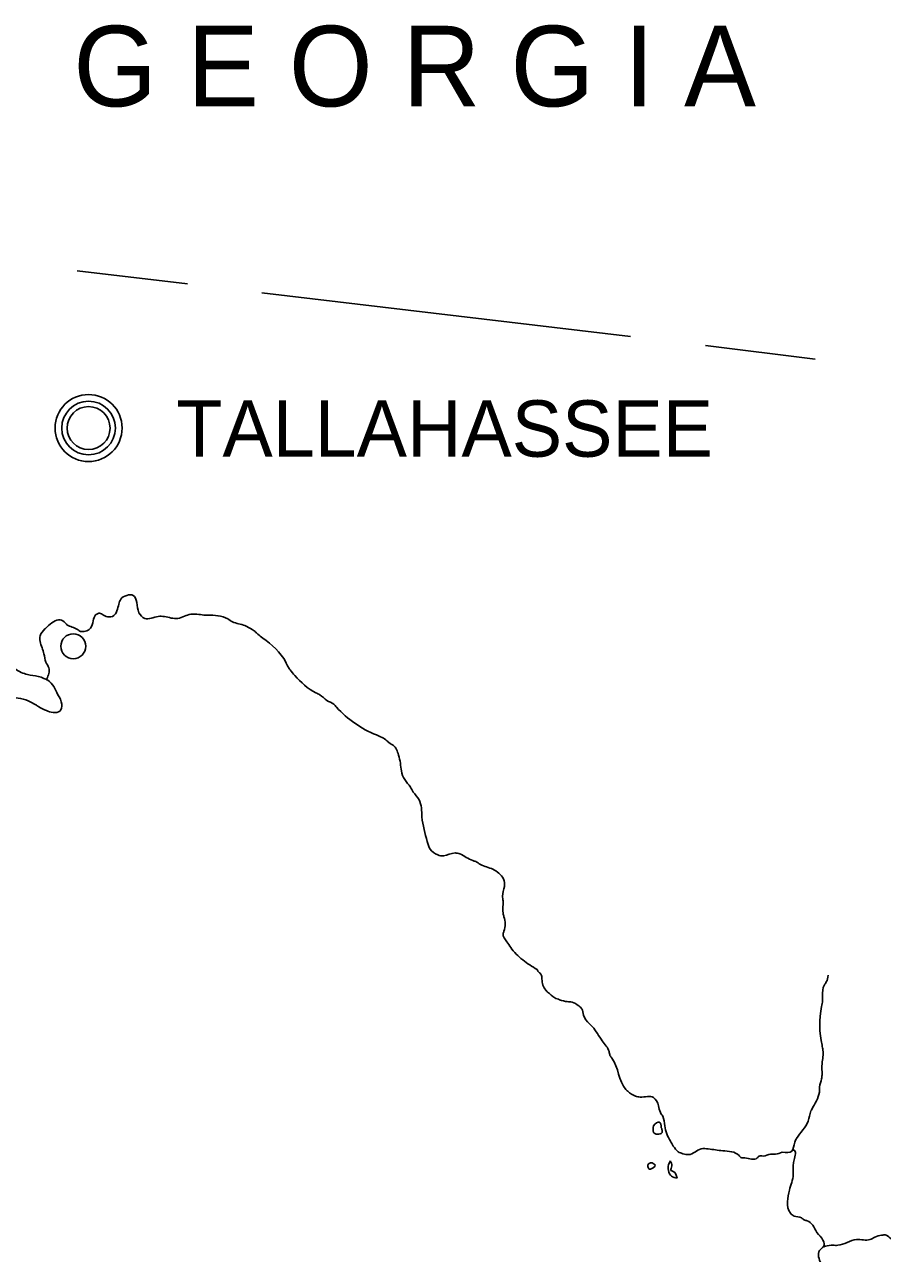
# Model space of a CAD drawing. Extents: x 384865 to 516869, y 1553900 to 1655899.
# Drawn here: x 485644 to 490473, y 1641531 to 1648449 of the extents above; entities that cross this region are included whole.
import ezdxf

# ---------------------------------------------------------------- set-up
doc = ezdxf.new("R2010")
doc.units = 0
doc.layers.add('V-ANNO-SYMB', color=7, linetype='Continuous')

msp = doc.modelspace()

# ---------------------------------------------------------------- linework, layer by layer
at = {"layer": 'V-ANNO-SYMB'}
for p, q in [((486561.4047428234, 1646989.260452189), (485939.67034240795, 1647062.938050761)), ((489053.9745422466, 1646692.9678515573), (486980.0559425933, 1646938.2142518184)), ((490093.7391423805, 1646564.1724524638), (489476.09794269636, 1646641.9432530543)), ((485831.44354296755, 1644676.0840512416), (485828.74354296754, 1644678.7840512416))]:
    msp.add_line(p, q, dxfattribs=at)
for centre, radius in [((486004.167942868, 1646177.2840512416), 188.66823551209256), ((486004.167942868, 1646177.2840512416), 150.9345884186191), ((486004.167942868, 1646177.2840512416), 120.74767074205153), ((485917.76794329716, 1644948.7840512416), 70.19999999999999)]:
    msp.add_circle(centre, radius, dxfattribs=at)
for points in [[(485769.3435429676, 1644765.1840512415), (485780.1435433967, 1644794.8840512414), (485780.14354296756, 1644827.2840512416), (485763.94354296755, 1644859.6840521), (485753.1435433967, 1644905.5840512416), (485731.5435429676, 1644975.7840512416), (485731.5435429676, 1645008.1840512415), (485758.5435429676, 1645045.9840512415), (485769.34354339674, 1645056.7840520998), (485807.1435425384, 1645086.4840512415), (485844.94354296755, 1645097.2840512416), (485871.94354296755, 1645081.0840520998), (485882.74354296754, 1645070.2840520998), (485942.14354296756, 1645043.2840529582), (485958.3435425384, 1645032.4840512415), (485979.9435425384, 1645032.4840512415), (486006.94354296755, 1645043.2840512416), (486028.5435429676, 1645081.0840520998), (486039.34354339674, 1645118.8840512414), (486050.1435425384, 1645129.6840512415), (486066.3435429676, 1645135.0840520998), (486087.94354296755, 1645124.2840512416), (486120.3435429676, 1645113.4840512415), (486152.74354296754, 1645126.9840512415), (486163.5435429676, 1645148.5840520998), (486174.3435425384, 1645186.3840512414), (486185.1435425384, 1645213.384052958), (486255.3435425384, 1645234.9840512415), (486287.7435433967, 1645137.7840520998), (486320.14354296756, 1645105.3840512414), (486395.74354296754, 1645116.1840512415), (486430.8435429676, 1645116.1840512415), (486506.4435433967, 1645105.3840521), (486544.24354296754, 1645118.8840512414), (486614.4435421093, 1645129.6840512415), (486652.24354253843, 1645124.2840512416), (486673.8435429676, 1645124.2840520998), (486787.24354253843, 1645102.6840521), (486814.24354253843, 1645086.4840512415), (486884.44354296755, 1645064.8840521), (486924.9435433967, 1645043.2840512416), (486946.5435425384, 1645027.0840520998), (486957.3435429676, 1645016.2840512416), (486984.3435429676, 1644994.6840512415), (487113.9435433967, 1644859.6840512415), (487127.4435425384, 1644832.6840512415), (487138.24354296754, 1644816.4840520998), (487165.24354296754, 1644784.0840512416), (487284.0435429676, 1644686.8840521), (487305.64354296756, 1644676.0840512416), (487346.14354296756, 1644643.6840512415), (487383.94354296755, 1644622.0840520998), (487400.1435433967, 1644605.8840512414), (487624.24354296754, 1644449.2840520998), (487683.6435425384, 1644416.8840512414), (487694.44354296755, 1644406.0840520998), (487721.4435425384, 1644389.8840512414), (487737.64354296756, 1644368.2840512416), (487748.44354296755, 1644335.8840521), (487759.24354296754, 1644289.9840512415), (487764.64354296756, 1644246.7840512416), (487783.5435429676, 1644198.1840521), (487815.94354296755, 1644154.9840512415), (487832.14354296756, 1644127.9840512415), (487864.5435433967, 1644084.7840520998), (487880.7435433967, 1643987.5840520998), (487910.44354296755, 1643849.884052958), (487926.6435433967, 1643806.6840512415), (487969.8435429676, 1643774.2840512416), (488002.24354296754, 1643768.8840512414), (488067.0435429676, 1643785.0840512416), (488094.0435429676, 1643779.6840521), (488166.94354296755, 1643741.8840512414), (488183.14354296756, 1643736.4840520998), (488210.14354296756, 1643720.2840512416), (488280.3435429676, 1643693.2840529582), (488312.74354253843, 1643671.6840512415), (488339.74354296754, 1643639.2840529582), (488345.14354296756, 1643596.0840520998), (488334.3435429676, 1643542.0840520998), (488337.0435433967, 1643515.0840512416), (488337.0435433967, 1643444.8840521), (488342.4435433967, 1643425.9840520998), (488342.44354296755, 1643344.9840520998), (488337.0435429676, 1643328.7840529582), (488358.64354296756, 1643285.5840520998), (488380.24354296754, 1643253.1840512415), (488447.74354296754, 1643182.9840512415), (488528.74354296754, 1643128.9840520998)], [(485831.44354296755, 1644676.0840512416), (485774.74354253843, 1644757.0840520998), (485753.1435425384, 1644767.8840521), (485720.74354253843, 1644778.6840512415), (485661.3435429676, 1644789.4840512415), (485591.14354296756, 1644821.8840512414), (485574.9435425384, 1644832.6840512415), (485547.9435433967, 1644838.0840512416), (485515.5435429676, 1644848.8840521), (485477.74354296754, 1644854.2840512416), (485418.3435425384, 1644854.2840512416), (485372.4435433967, 1644846.1840512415), (485350.8435429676, 1644873.1840512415), (485345.4435425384, 1644889.3840512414), (485269.8435425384, 1644932.5840520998), (485242.84354339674, 1644943.3840512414), (485167.24354296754, 1645002.7840512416), (485140.24354296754, 1645018.9840512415), (485115.94354296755, 1645040.5840512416), (485094.34354339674, 1645064.8840512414), (485061.94354296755, 1645108.0840512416)], [(484092.6435425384, 1644138.7840512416), (484108.8435429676, 1644165.7840512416), (484130.4435433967, 1644160.3840512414), (484168.24354296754, 1644165.7840512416), (484200.6435433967, 1644176.5840512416), (484216.84354339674, 1644200.8840512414), (484243.8435425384, 1644308.8840512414), (484270.8435425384, 1644325.0840512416), (484308.6435425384, 1644308.8840512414), (484341.0435425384, 1644308.8840521), (484373.4435433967, 1644349.3840512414), (484384.24354296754, 1644360.1840512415), (484389.6435433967, 1644322.3840512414), (484389.64354296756, 1644265.6840512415), (484376.14354296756, 1644217.0840512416), (484370.74354296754, 1644190.0840512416), (484370.74354296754, 1644163.0840512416), (484413.9435433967, 1644195.4840512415), (484440.9435425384, 1644238.6840512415), (484484.1435433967, 1644257.5840512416), (484619.14354296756, 1644257.5840520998), (484651.5435429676, 1644273.7840512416), (484716.3435425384, 1644338.5840512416), (484732.5435429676, 1644352.0840512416), (484759.5435429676, 1644368.2840512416), (484770.3435429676, 1644384.4840512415), (484829.74354296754, 1644422.2840512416), (484899.94354296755, 1644449.2840512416), (484943.1435425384, 1644468.1840512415), (485007.94354296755, 1644505.9840512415), (485229.3435429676, 1644584.2840512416), (485250.94354296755, 1644595.0840512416), (485564.14354296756, 1644657.1840512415), (485607.34354339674, 1644657.1840512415), (485664.0435429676, 1644640.9840512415), (485707.2435433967, 1644619.3840512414), (485723.4435433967, 1644608.5840512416), (485766.64354296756, 1644586.9840512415), (485804.4435425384, 1644576.1840512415), (485842.24354296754, 1644584.2840512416), (485853.0435433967, 1644622.0840512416), (485831.44354296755, 1644676.0840512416)], [(488528.74354296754, 1643128.9840520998), (488539.5435433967, 1643112.7840512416), (488550.3435429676, 1643101.9840512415), (488555.74354296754, 1643074.9840520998), (488577.34354382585, 1643012.8840512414), (488588.14354296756, 1643002.0840520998), (488628.6435433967, 1642969.6840521), (488655.64354296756, 1642958.884052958), (488698.84354339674, 1642948.0840520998), (488725.8435429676, 1642945.3840512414), (488763.6435433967, 1642923.7840512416), (488779.8435429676, 1642907.5840512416), (488790.6435438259, 1642872.4840520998), (488823.0435429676, 1642823.8840512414), (488839.2435433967, 1642807.6840512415), (488895.94354296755, 1642726.6840512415), (488933.74354296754, 1642667.2840520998), (488939.1435433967, 1642645.6840512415), (488949.94354296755, 1642629.4840529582), (489028.24354296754, 1642453.9840512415), (489039.0435429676, 1642443.1840521), (489082.2435433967, 1642416.1840521), (489109.2435433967, 1642410.7840520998), (489184.84354339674, 1642408.0840512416), (489211.8435429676, 1642362.1840521), (489222.6435433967, 1642324.384052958), (489236.1435438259, 1642302.7840512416), (489246.9435433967, 1642248.7840520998), (489279.3435429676, 1642162.384052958), (489295.5435433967, 1642135.384052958), (489322.5435433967, 1642102.9840520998), (489349.5435429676, 1642092.1840512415), (489381.94354296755, 1642086.7840529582), (489452.1435425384, 1642119.1840521), (489492.64354296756, 1642119.1840512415), (489573.6435433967, 1642108.3840512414), (489665.4435438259, 1642081.3840521), (489676.24354382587, 1642070.5840520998), (489697.8435429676, 1642067.8840512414), (489768.0435433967, 1642067.884052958), (489778.8435429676, 1642078.6840521), (489800.44354296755, 1642078.6840512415), (489843.64354296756, 1642089.4840520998), (489870.6435438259, 1642089.4840529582), (489908.4435438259, 1642100.2840512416)], [(489908.4435438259, 1642100.2840512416), (489962.4435433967, 1642105.6840512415), (489978.6435433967, 1642156.9840529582), (489989.4435433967, 1642178.5840520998), (490054.24354296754, 1642275.7840512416), (490070.4435433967, 1642332.4840512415), (490081.24354296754, 1642354.084052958), (490119.0435429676, 1642451.2840520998), (490119.0435433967, 1642467.4840520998), (490129.8435429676, 1642513.384052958), (490132.5435429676, 1642534.9840512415), (490132.5435425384, 1642599.7840529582), (490137.94354296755, 1642637.584052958), (490137.9435438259, 1642675.384052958), (490132.5435433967, 1642702.3840521), (490129.84354339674, 1642921.0840520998), (490135.24354296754, 1642953.4840512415), (490135.24354253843, 1642980.4840529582), (490146.0435433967, 1643042.584052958), (490156.84354339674, 1643058.7840520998), (490167.6435433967, 1643096.5840520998)], [(489184.84354339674, 1642210.9840520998), (489184.84354339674, 1642248.7840512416), (489217.24354296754, 1642270.3840521), (489228.04354382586, 1642237.9840512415)], [(489184.84354339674, 1642210.9840520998), (489198.3435429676, 1642202.8840512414), (489214.5435429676, 1642202.8840521), (489228.0435433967, 1642205.584052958), (489233.4435433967, 1642219.0840512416), (489228.04354382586, 1642237.9840512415)], [(489970.5435433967, 1642111.0840520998), (489973.2435433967, 1642111.084052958), (489975.9435433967, 1642057.0840520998), (489970.5435433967, 1642030.0840512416), (489970.54354382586, 1641976.084052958), (489948.94354296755, 1641886.9840529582), (489938.14354296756, 1641822.1840521), (489954.3435425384, 1641757.3840521), (489975.9435433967, 1641741.1840529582), (490016.4435433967, 1641730.3840521), (490032.6435433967, 1641719.5840520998), (490048.84354339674, 1641714.1840521), (490102.84354339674, 1641649.384052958)], [(489192.9435433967, 1642030.0840520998), (489187.5435433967, 1642016.5840520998), (489174.0435429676, 1642008.4840529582), (489160.5435433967, 1642005.7840529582), (489152.4435433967, 1642019.2840529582), (489155.1435433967, 1642035.4840529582)], [(489155.1435433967, 1642035.4840529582), (489171.3435429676, 1642040.8840521), (489192.9435433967, 1642030.0840520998)], [(489279.34354339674, 1642051.6840529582), (489268.54354382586, 1642030.0840520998), (489268.5435433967, 1641997.6840529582), (489284.7435433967, 1641965.2840512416), (489317.1435433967, 1641954.4840520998)], [(489279.34354339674, 1642051.6840529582), (489284.7435433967, 1642038.1840512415), (489287.4435438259, 1642024.6840529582), (489282.0435433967, 1641997.6840521), (489295.5435433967, 1641992.2840520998), (489317.1435433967, 1641954.4840520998)], [(490102.84354339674, 1641649.384052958), (490140.6435433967, 1641568.3840512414), (490119.0435433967, 1641546.7840529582), (490113.6435433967, 1641511.6840521), (490127.1435433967, 1641473.884052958), (490154.1435433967, 1641430.6840521), (490186.5435433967, 1641403.6840529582), (490224.34354339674, 1641382.084052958), (490235.1435433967, 1641371.2840529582), (490256.74354382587, 1641338.884052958), (490262.1435438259, 1641295.6840521), (490262.1435433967, 1641268.6840521), (490272.9435433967, 1641230.8840521), (490291.84354339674, 1641209.2840529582), (490329.6435438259, 1641176.884052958), (490356.6435438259, 1641166.0840520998), (490405.24354382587, 1641155.2840529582), (490426.8435429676, 1641139.084052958), (490432.2435433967, 1641093.1840521), (490421.4435438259, 1641071.5840520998), (490410.64354296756, 1641055.384052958), (490389.0435433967, 1641033.7840529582), (490318.84354339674, 1641012.1840529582), (490291.84354382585, 1640990.584052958), (490270.2435433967, 1640933.8840521), (490270.2435433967, 1640912.2840520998), (490264.84354382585, 1640879.884052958), (490305.34354382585, 1640739.4840520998), (490316.1435433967, 1640701.6840521), (490326.9435433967, 1640677.384052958), (490337.7435433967, 1640639.584052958), (490353.9435438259, 1640601.7840529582), (490362.0435433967, 1640504.5840512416), (490362.0435433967, 1640461.384052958), (490356.6435433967, 1640420.8840521), (490356.6435438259, 1640383.084052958), (490351.24354425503, 1640366.884052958), (490351.2435433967, 1640339.884052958), (490345.84354339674, 1640312.8840512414), (490345.84354382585, 1640291.2840529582), (490337.7435433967, 1640045.5840520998), (490332.3435429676, 1640007.7840520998), (490316.14354296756, 1639980.7840529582), (490256.74354382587, 1639907.8840512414), (490251.34354382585, 1639880.884052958), (490245.94354425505, 1639864.6840529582), (490243.24354382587, 1639732.384052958), (490210.84354382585, 1639662.1840512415), (490205.4435438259, 1639629.7840512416), (490173.04354382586, 1639556.8840521), (490135.2435433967, 1639443.4840520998), (490119.04354382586, 1639411.0840512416), (490108.2435433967, 1639394.8840521), (490100.1435438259, 1639370.584052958), (490040.7435433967, 1639284.1840529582), (490029.9435438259, 1639262.5840520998), (490008.3435429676, 1639230.1840521), (489986.74354382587, 1639168.084052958), (489970.54354382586, 1639141.084052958), (489943.54354382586, 1639065.4840520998), (489932.74354382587, 1639027.6840512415), (489911.1435438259, 1638997.9840512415), (489900.34354339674, 1638976.3840512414), (489900.34354382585, 1638933.1840521), (489908.44354425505, 1638911.5840520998), (489913.84354382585, 1638889.9840512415), (489913.84354382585, 1638862.9840529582), (489919.24354382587, 1638819.7840520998), (489919.24354425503, 1638792.7840520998), (489897.6435438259, 1638676.6840521), (489897.643544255, 1638638.8840512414), (489892.24354425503, 1638606.4840512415), (489894.94354425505, 1638533.5840520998), (489889.543544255, 1638501.1840521), (489889.54354382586, 1638474.1840521), (489884.1435438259, 1638430.9840520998), (489884.1435438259, 1638409.3840521), (489854.44354425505, 1638190.6840512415), (489816.643544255, 1638085.3840521), (489778.843544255, 1638020.5840520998), (489768.04354382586, 1637982.7840520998), (489768.04354382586, 1637923.3840512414), (489789.6435433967, 1637872.0840512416), (489800.44354425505, 1637861.2840529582), (489824.74354382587, 1637807.2840520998), (489840.94354425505, 1637780.2840529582), (489911.1435438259, 1637796.4840512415), (489948.94354425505, 1637788.3840521), (489970.543544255, 1637726.2840529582), (489981.34354382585, 1637710.084052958), (489997.543544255, 1637666.884052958)], [(490143.34354339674, 1641568.3840521), (490151.4435433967, 1641571.0840520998), (490194.6435438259, 1641576.4840529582), (490221.64354296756, 1641576.4840529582), (490326.94354296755, 1641608.8840512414), (490402.5435429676, 1641608.8840521), (490429.5435433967, 1641622.3840521), (490467.34354339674, 1641633.1840529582), (490494.34354339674, 1641633.1840512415), (490548.34354339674, 1641595.384052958), (490569.9435438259, 1641600.7840529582), (490602.34354339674, 1641643.9840512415), (490645.5435433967, 1641665.584052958), (490677.9435433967, 1641660.1840521), (490710.3435429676, 1641643.9840529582)]]:
    msp.add_spline(points, degree=3, dxfattribs=at)

# ---------------------------------------------------------------- texts
for s, height, p in [('G E O R G I A', 453.59999999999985, (485918.28294330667, 1647988.1866223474)), ('TALLAHASSEE', 317.5199999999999, (486498.3958357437, 1646015.716661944))]:
    msp.add_text(s, height=height, rotation=8.564476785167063e-09, dxfattribs=at).set_placement(p)

doc.saveas('drawing.dxf')
